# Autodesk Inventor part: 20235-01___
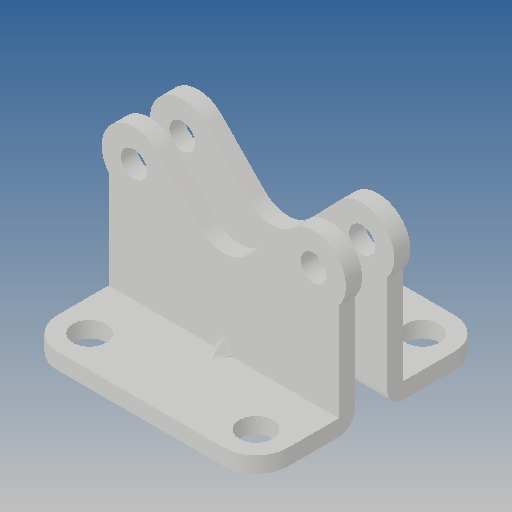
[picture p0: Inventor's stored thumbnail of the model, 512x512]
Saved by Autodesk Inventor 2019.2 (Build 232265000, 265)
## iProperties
Created: 2010-06
Part Number: 20235-01___
Material: Ogólny
Document SubType Name: Modeling
Designer: CADENGINEERING4
Density: 1 g/cm^3
Appearance: Domyślna
Author: CADENGINEERING4
Revision Number: ANY
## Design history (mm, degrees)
feature "NONE"
feature "NONE:1"
node "Bryła1"
node "Bryła2"
